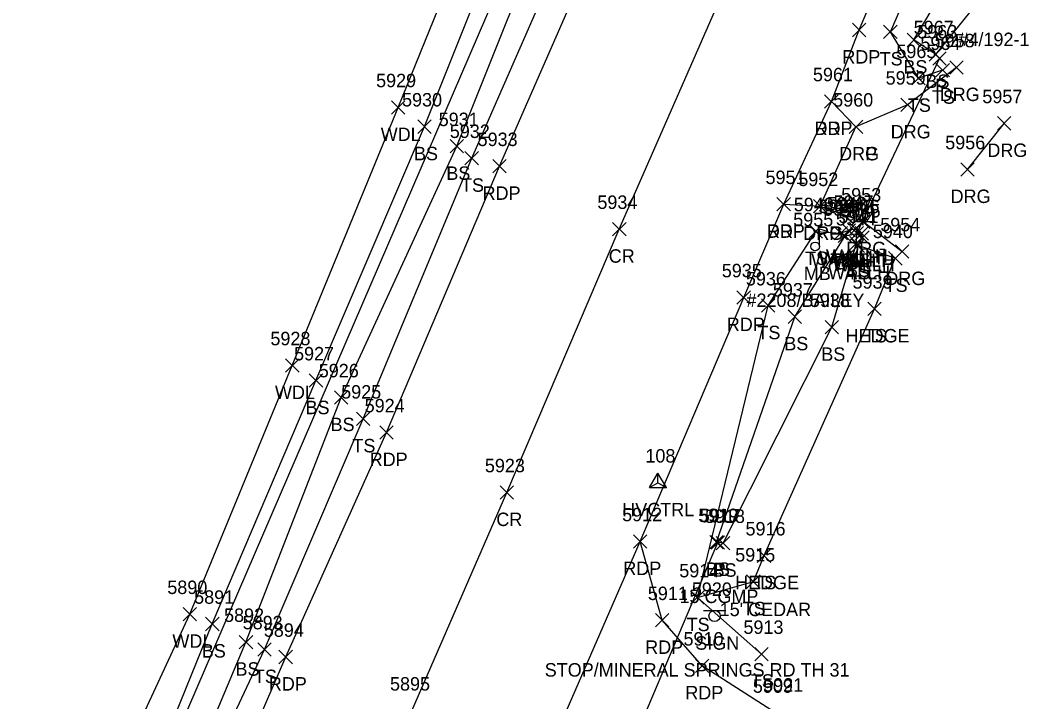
# Model space of a CAD drawing. Extents: x 1611797 to 1633212, y 298978 to 305475.
# Drawn here: x 1622670.8 to 1622821.6, y 301645.8 to 301747.1 of the extents above; entities that cross this region are included whole.
import ezdxf

# ---------------------------------------------------------------- set-up
doc = ezdxf.new("R2010")
doc.units = 0
for name, color, linetype in [('C_A', 7, 'Continuous'), ('C_I', 7, 'Continuous'), ('CPSM', 7, 'Continuous'), ('D_A', 7, 'Continuous'), ('D_C', 7, 'Continuous'), ('D_I', 7, 'Continuous'), ('D_TIC', 7, 'Continuous'), ('DCP', 7, 'Continuous'), ('DHW', 7, 'Continuous'), ('L_A', 7, 'Continuous'), ('L_C', 7, 'Continuous'), ('L_I', 7, 'Continuous'), ('L_TIC', 7, 'Continuous'), ('LAHR', 7, 'Continuous'), ('LAWA', 7, 'Continuous'), ('LELB', 7, 'Continuous'), ('LMB', 7, 'Continuous'), ('P_A', 7, 'Continuous'), ('P_I', 7, 'Continuous'), ('P_TIC', 7, 'Continuous'), ('PET', 7, 'Continuous'), ('PRC', 7, 'Continuous'), ('R_A', 7, 'Continuous'), ('R_I', 7, 'Continuous'), ('R_TIC', 7, 'Continuous'), ('RDG', 7, 'Continuous'), ('RDP', 7, 'Continuous'), ('S_A', 7, 'Continuous'), ('S_C', 7, 'Continuous'), ('S_I', 7, 'Continuous'), ('SSGN', 7, 'Continuous'), ('U_C', 7, 'Continuous')]:
    doc.layers.add(name, color=color, linetype=linetype)

msp = doc.modelspace()

# ---------------------------------------------------------------- linework, layer by layer
at = {"layer": 'CPSM'}
for p, q in [((1622764.35, 301677.62), (1622765.6, 301679.78)), ((1622766.85, 301677.62), (1622765.6, 301679.78)), ((1622765.6, 301678.34), (1622765.6, 301679.78)), ((1622764.35, 301677.62), (1622765.6, 301678.34)), ((1622765.6, 301678.34), (1622765.6, 301678.34)), ((1622765.6, 301678.34), (1622766.85, 301677.62)), ((1622764.35, 301677.62), (1622766.85, 301677.62))]:
    msp.add_line(p, q, dxfattribs=at)
at = {"layer": 'D_TIC'}
for points in [[(1622806.46, 301740.42), (1622808.46, 301742.42)], [(1622808.46, 301740.42), (1622806.46, 301742.42)], [(1622793.98, 301715.07), (1622795.98, 301717.07)], [(1622795.98, 301715.07), (1622793.98, 301717.07)], [(1622791.81, 301714.45), (1622793.81, 301716.45)], [(1622793.81, 301714.45), (1622791.81, 301716.45)], [(1622792.98, 301714.84), (1622794.98, 301716.84)], [(1622794.98, 301714.84), (1622792.98, 301716.84)], [(1622794.17, 301714.43), (1622796.17, 301716.43)], [(1622796.17, 301714.43), (1622794.17, 301716.43)], [(1622794.91, 301714.43), (1622796.91, 301716.43)], [(1622796.91, 301714.43), (1622794.91, 301716.43)], [(1622795.02, 301713.8), (1622797.02, 301715.8)], [(1622797.02, 301713.8), (1622795.02, 301715.8)], [(1622794.32, 301712.6), (1622796.32, 301714.6)], [(1622796.32, 301712.6), (1622794.32, 301714.6)], [(1622773.51, 301668.44), (1622775.51, 301670.44)], [(1622775.51, 301668.44), (1622773.51, 301670.44)]]:
    msp.add_lwpolyline(points, dxfattribs=at)
at = {"layer": 'DCP'}
for points in [[(1622671.2, 301587.84), (1622827.38, 301950.3)], [(1622795.17, 301715.43), (1622807.46, 301741.42)], [(1622757.09, 301628.39), (1622774.51, 301669.44)]]:
    msp.add_lwpolyline(points, dxfattribs=at)
at = {"layer": 'DHW'}
msp.add_lwpolyline([(1622795.32, 301713.6), (1622796.02, 301714.8), (1622795.91, 301715.43), (1622794.98, 301716.07), (1622793.98, 301715.84), (1622792.81, 301715.45)], dxfattribs=at)
at = {"layer": 'L_TIC'}
for points in [[(1622799.16, 301744.4), (1622801.16, 301746.4)], [(1622801.16, 301744.4), (1622799.16, 301746.4)], [(1622802.66, 301743.19), (1622804.66, 301745.19)], [(1622804.66, 301743.19), (1622802.66, 301745.19)], [(1622805.93, 301741.05), (1622807.93, 301743.05)], [(1622807.93, 301741.05), (1622805.93, 301743.05)], [(1622805.93, 301741.05), (1622807.93, 301743.05)], [(1622807.93, 301741.05), (1622805.93, 301743.05)], [(1622806.94, 301738.7), (1622808.94, 301740.7)], [(1622808.94, 301738.7), (1622806.94, 301740.7)], [(1622803.35, 301737.5), (1622805.35, 301739.5)], [(1622805.35, 301737.5), (1622803.35, 301739.5)], [(1622725.95, 301733.16), (1622727.95, 301735.16)], [(1622727.95, 301733.16), (1622725.95, 301735.16)], [(1622729.88, 301730.3), (1622731.88, 301732.3)], [(1622731.88, 301730.3), (1622729.88, 301732.3)], [(1622734.69, 301727.38), (1622736.69, 301729.38)], [(1622736.69, 301727.38), (1622734.69, 301729.38)], [(1622736.9, 301725.61), (1622738.9, 301727.61)], [(1622738.9, 301725.61), (1622736.9, 301727.61)], [(1622788.07, 301714.72), (1622790.07, 301716.72)], [(1622790.07, 301714.72), (1622788.07, 301716.72)], [(1622791.81, 301714.45), (1622793.81, 301716.45)], [(1622793.81, 301714.45), (1622791.81, 301716.45)], [(1622792.42, 301714.05), (1622794.42, 301716.05)], [(1622794.42, 301714.05), (1622792.42, 301716.05)], [(1622794.17, 301714.43), (1622796.17, 301716.43)], [(1622796.17, 301714.43), (1622794.17, 301716.43)], [(1622794.17, 301714.43), (1622796.17, 301716.43)], [(1622796.17, 301714.43), (1622794.17, 301716.43)], [(1622794.13, 301712.96), (1622796.13, 301714.96)], [(1622796.13, 301712.96), (1622794.13, 301714.96)], [(1622794.32, 301712.6), (1622796.32, 301714.6)], [(1622796.32, 301712.6), (1622794.32, 301714.6)], [(1622799.9, 301710.72), (1622801.9, 301712.72)], [(1622801.9, 301710.72), (1622799.9, 301712.72)], [(1622780.99, 301703.68), (1622782.99, 301705.68)], [(1622782.99, 301703.68), (1622780.99, 301705.68)], [(1622796.81, 301703.2), (1622798.81, 301705.2)], [(1622798.81, 301703.2), (1622796.81, 301705.2)], [(1622796.81, 301703.2), (1622798.81, 301705.2)], [(1622798.81, 301703.2), (1622796.81, 301705.2)], [(1622784.95, 301702.03), (1622786.95, 301704.03)], [(1622786.95, 301702.03), (1622784.95, 301704.03)], [(1622790.45, 301700.47), (1622792.45, 301702.47)], [(1622792.45, 301700.47), (1622790.45, 301702.47)], [(1622710.22, 301694.78), (1622712.22, 301696.78)], [(1622712.22, 301694.78), (1622710.22, 301696.78)], [(1622713.74, 301692.53), (1622715.74, 301694.53)], [(1622715.74, 301692.53), (1622713.74, 301694.53)], [(1622717.47, 301690.01), (1622719.47, 301692.01)], [(1622719.47, 301690.01), (1622717.47, 301692.01)], [(1622720.75, 301686.85), (1622722.75, 301688.85)], [(1622722.75, 301686.85), (1622720.75, 301688.85)], [(1622773.3, 301668.48), (1622775.3, 301670.48)], [(1622775.3, 301668.48), (1622773.3, 301670.48)], [(1622774.28, 301668.35), (1622776.28, 301670.35)], [(1622776.28, 301668.35), (1622774.28, 301670.35)], [(1622774.28, 301668.35), (1622776.28, 301670.35)], [(1622776.28, 301668.35), (1622774.28, 301670.35)], [(1622780.37, 301666.49), (1622782.37, 301668.49)], [(1622782.37, 301666.49), (1622780.37, 301668.49)], [(1622780.37, 301666.49), (1622782.37, 301668.49)], [(1622782.37, 301666.49), (1622780.37, 301668.49)], [(1622778.79, 301662.62), (1622780.79, 301664.62)], [(1622780.79, 301662.62), (1622778.79, 301664.62)], [(1622770.46, 301660.26), (1622772.46, 301662.26)], [(1622772.46, 301660.26), (1622770.46, 301662.26)], [(1622770.46, 301660.26), (1622772.46, 301662.26)], [(1622772.46, 301660.26), (1622770.46, 301662.26)], [(1622694.98, 301657.78), (1622696.98, 301659.78)], [(1622696.98, 301657.78), (1622694.98, 301659.78)], [(1622698.32, 301656.33), (1622700.32, 301658.33)], [(1622700.32, 301656.33), (1622698.32, 301658.33)], [(1622703.33, 301653.63), (1622705.33, 301655.63)], [(1622705.33, 301653.63), (1622703.33, 301655.63)], [(1622706.1, 301652.53), (1622708.1, 301654.53)], [(1622708.1, 301652.53), (1622706.1, 301654.53)], [(1622780, 301651.85), (1622782, 301653.85)], [(1622782, 301651.85), (1622780, 301653.85)]]:
    msp.add_lwpolyline(points, dxfattribs=at)
at = {"layer": 'LAHR'}
msp.add_lwpolyline([(1622781.37, 301667.49), (1622797.81, 301704.2)], dxfattribs=at)
at = {"layer": 'LAWA'}
msp.add_lwpolyline([(1622629.31, 301519.57), (1622648.55, 301554.37), (1622664.62, 301587.8), (1622679.92, 301624.12), (1622695.98, 301658.78), (1622711.22, 301695.78), (1622726.95, 301734.16), (1622740.87, 301768.52), (1622755.14, 301811.42), (1622771.04, 301843.63), (1622788.09, 301881.91), (1622808.18, 301922.72), (1622823.47, 301955.6), (1622839.78, 301995.94), (1622853.69, 302036.53), (1622871.34, 302077.8), (1622889.2, 302115.36), (1622900.36, 302148.59), (1622922.7, 302194.91), (1622935.02, 302227), (1622955.61, 302269.3), (1622974.66, 302322.11)], dxfattribs=at)
at = {"layer": 'LELB'}
for points in [[(1622643, 301512.06), (1622661.31, 301549.35), (1622677.51, 301586.51), (1622691.37, 301620.02), (1622707.1, 301653.53), (1622721.75, 301687.85), (1622737.9, 301726.61), (1622754.91, 301765.49), (1622771.04, 301804.05), (1622784.95, 301836.58), (1622802.84, 301876.81), (1622819.3, 301916.18), (1622833.77, 301948.78), (1622851.03, 301989.78), (1622867.88, 302029.76), (1622885.49, 302071.56), (1622902.14, 302111.43), (1622917.02, 302143.8), (1622935.82, 302186.87), (1622950.2, 302222.12), (1622969.04, 302263.04)], [(1622807.94, 301739.7), (1622804.35, 301738.5), (1622800.16, 301745.4), (1622817.14, 301784.47), (1622830.39, 301816.56), (1622848.44, 301857.01), (1622864.13, 301895.69), (1622879.47, 301932.48), (1622894.46, 301967.7), (1622913.22, 302010.21), (1622930.46, 302050.66), (1622949.02, 302093.66), (1622977.04, 302156.2), (1622983.26, 302165.57), (1622999.14, 302167.9)], [(1622594.68, 301439.81), (1622595.31, 301437.14), (1622596.39, 301436.56), (1622598.61, 301436.87), (1622605.11, 301452.44), (1622623.3, 301484.96), (1622638.71, 301514.37), (1622656.97, 301550.94), (1622672.9, 301585.85), (1622690.2, 301620.98), (1622704.33, 301654.63), (1622718.47, 301691.01), (1622735.69, 301728.38), (1622751, 301766.72), (1622767.76, 301805.21), (1622781.52, 301838.57), (1622799.78, 301877.75), (1622815.96, 301917.88), (1622831.89, 301949.85), (1622847.11, 301991.62), (1622864.58, 302030.86), (1622881.19, 302073.91), (1622897.69, 302112.61), (1622900.36, 302148.59)], [(1622594.68, 301439.81), (1622601.87, 301453.13), (1622619.23, 301487.68), (1622635.73, 301516.83), (1622653.65, 301552.16), (1622669.95, 301587.77), (1622685.32, 301622.84), (1622699.32, 301657.33), (1622714.74, 301693.53), (1622730.88, 301731.3), (1622746.12, 301769.47), (1622759.32, 301807.94), (1622775.78, 301841.76), (1622793.88, 301879.63), (1622811.29, 301920.97), (1622825.77, 301951.79), (1622844.08, 301994.2), (1622859.8, 302033.13), (1622878.46, 302076.5), (1622894.74, 302113.74), (1622900.36, 302148.59)], [(1622806.93, 301742.05), (1622803.66, 301744.19), (1622825.75, 301781.18), (1622835.8, 301814.35)], [(1622806.93, 301742.05), (1622835.85, 301777.79)], [(1622781, 301652.85), (1622771.46, 301661.26), (1622781.99, 301704.68), (1622789.07, 301715.72), (1622792.81, 301715.45)], [(1622775.28, 301669.35), (1622774.3, 301669.48), (1622785.95, 301703.03), (1622793.42, 301715.05), (1622795.17, 301715.43)], [(1622775.28, 301669.35), (1622791.45, 301701.47), (1622795.13, 301713.96), (1622795.17, 301715.43)], [(1622797.81, 301704.2), (1622800.9, 301711.72), (1622795.32, 301713.6)], [(1622771.46, 301661.26), (1622779.79, 301663.62), (1622781.37, 301667.49)]]:
    msp.add_lwpolyline(points, dxfattribs=at)
at = {"layer": 'LMB'}
for p, q in [((1622789.63, 301716.08), (1622790.93, 301715.7)), ((1622789.64, 301713.49), (1622789.64, 301716.08)), ((1622789.64, 301715.18), (1622790.92, 301715.69)), ((1622788.98, 301713.48), (1622788.98, 301713.48))]:
    msp.add_line(p, q, dxfattribs=at)
msp.add_circle((1622788.98, 301713.48), 0.656, dxfattribs=at)
at = {"layer": 'P_TIC'}
for points in [[(1622794.53, 301744.68), (1622796.53, 301746.68)], [(1622796.53, 301744.68), (1622794.53, 301746.68)], [(1622790.39, 301734.05), (1622792.39, 301736.05)], [(1622792.39, 301734.05), (1622790.39, 301736.05)], [(1622741.04, 301724.41), (1622743.04, 301726.41)], [(1622743.04, 301724.41), (1622741.04, 301726.41)], [(1622783.3, 301718.76), (1622785.3, 301720.76)], [(1622785.3, 301718.76), (1622783.3, 301720.76)], [(1622758.85, 301715.06), (1622760.85, 301717.06)], [(1622760.85, 301715.06), (1622758.85, 301717.06)], [(1622777.35, 301704.89), (1622779.35, 301706.89)], [(1622779.35, 301704.89), (1622777.35, 301706.89)], [(1622724.24, 301684.81), (1622726.24, 301686.81)], [(1622726.24, 301684.81), (1622724.24, 301686.81)], [(1622742.12, 301675.89), (1622744.12, 301677.89)], [(1622744.12, 301675.89), (1622742.12, 301677.89)], [(1622761.96, 301668.6), (1622763.96, 301670.6)], [(1622763.96, 301668.6), (1622761.96, 301670.6)], [(1622761.96, 301668.6), (1622763.96, 301670.6)], [(1622763.96, 301668.6), (1622761.96, 301670.6)], [(1622765.22, 301656.88), (1622767.22, 301658.88)], [(1622767.22, 301656.88), (1622765.22, 301658.88)], [(1622709.24, 301651.42), (1622711.24, 301653.42)], [(1622711.24, 301651.42), (1622709.24, 301653.42)], [(1622771.18, 301650.11), (1622773.18, 301652.11)], [(1622773.18, 301650.11), (1622771.18, 301652.11)]]:
    msp.add_lwpolyline(points, dxfattribs=at)
at = {"layer": 'PET'}
for points in [[(1622648.26, 301509.67), (1622665.21, 301547.65), (1622681.33, 301585.73), (1622695.37, 301617.98), (1622710.24, 301652.42), (1622725.24, 301685.81), (1622742.04, 301725.41), (1622758.88, 301763.93), (1622775.24, 301802.31), (1622789.18, 301834.69), (1622806.59, 301875.58), (1622823.24, 301913.81), (1622837.58, 301947.53), (1622854.56, 301988.08), (1622872.12, 302028.45), (1622889.38, 302069.51), (1622906.69, 302110.12), (1622920.84, 302142.69), (1622939.57, 302184.64), (1622954.91, 302220.6), (1622972.44, 302261.85)], [(1622698.78, 301521.43), (1622708.15, 301542.48), (1622718.91, 301567.6), (1622732.31, 301598.1), (1622748.3, 301635.86), (1622762.96, 301669.6), (1622778.35, 301705.89), (1622784.3, 301719.76), (1622791.39, 301735.05), (1622795.53, 301745.68), (1622812.78, 301786.17), (1622826.49, 301818.45), (1622843.67, 301858.56), (1622860.37, 301897.43), (1622876.1, 301933.63), (1622891.74, 301969.78), (1622909.96, 302011.85), (1622927.46, 302052.61), (1622945.32, 302094.8), (1622972.71, 302158.13)], [(1622748.3, 301635.86), (1622755.21, 301637.93), (1622765.81, 301636.97), (1622774.83, 301631.24), (1622783.06, 301644.09), (1622772.18, 301651.11), (1622766.22, 301657.88), (1622762.96, 301669.6)]]:
    msp.add_lwpolyline(points, dxfattribs=at)
at = {"layer": 'PRC'}
msp.add_lwpolyline([(1622666.77, 301501.34), (1622684.44, 301540.78), (1622698.59, 301575.31), (1622713.87, 301609.52), (1622729.01, 301644.42), (1622743.12, 301676.89), (1622759.85, 301716.06), (1622777.36, 301756.12), (1622793.76, 301794.22), (1622808.13, 301826.76), (1622825.32, 301867.31), (1622841.48, 301905.46), (1622856.61, 301940.95), (1622872.28, 301978.08), (1622890.25, 302020.71), (1622907.64, 302061.05), (1622925.87, 302103.21), (1622941.24, 302138.62), (1622957.15, 302175.75), (1622973.3, 302212.68)], dxfattribs=at)
at = {"layer": 'R_TIC'}
for points in [[(1622809.01, 301739.1), (1622811.01, 301741.1)], [(1622811.01, 301739.1), (1622809.01, 301741.1)], [(1622790.39, 301734.05), (1622792.39, 301736.05)], [(1622792.39, 301734.05), (1622790.39, 301736.05)], [(1622801.73, 301733.55), (1622803.73, 301735.55)], [(1622803.73, 301733.55), (1622801.73, 301735.55)], [(1622794.05, 301730.28), (1622796.05, 301732.28)], [(1622796.05, 301730.28), (1622794.05, 301732.28)], [(1622794.05, 301730.28), (1622796.05, 301732.28)], [(1622796.05, 301730.28), (1622794.05, 301732.28)], [(1622816.1, 301730.79), (1622818.1, 301732.79)], [(1622818.1, 301730.79), (1622816.1, 301732.79)], [(1622810.63, 301723.94), (1622812.63, 301725.94)], [(1622812.63, 301723.94), (1622810.63, 301725.94)], [(1622783.3, 301718.76), (1622785.3, 301720.76)], [(1622785.3, 301718.76), (1622783.3, 301720.76)], [(1622788.73, 301718.46), (1622790.73, 301720.46)], [(1622790.73, 301718.46), (1622788.73, 301720.46)], [(1622788.73, 301718.46), (1622790.73, 301720.46)], [(1622790.73, 301718.46), (1622788.73, 301720.46)], [(1622795.11, 301716.17), (1622797.11, 301718.17)], [(1622797.11, 301716.17), (1622795.11, 301718.17)], [(1622800.92, 301711.73), (1622802.92, 301713.73)], [(1622802.92, 301711.73), (1622800.92, 301713.73)]]:
    msp.add_lwpolyline(points, dxfattribs=at)
at = {"layer": 'RDG'}
for points in [[(1622810.01, 301740.1), (1622802.73, 301734.55), (1622795.05, 301731.28)], [(1622811.63, 301724.94), (1622817.1, 301731.79)], [(1622789.73, 301719.46), (1622796.11, 301717.17), (1622801.92, 301712.73)]]:
    msp.add_lwpolyline(points, dxfattribs=at)
at = {"layer": 'RDP'}
msp.add_lwpolyline([(1622784.3, 301719.76), (1622789.73, 301719.46), (1622795.05, 301731.28), (1622791.39, 301735.05)], dxfattribs=at)
at = {"layer": 'SSGN'}
for p, q in [((1622772.36, 301659.35), (1622775.7, 301659.35)), ((1622774.01, 301658.52), (1622774.01, 301658.52))]:
    msp.add_line(p, q, dxfattribs=at)
msp.add_circle((1622774.01, 301658.52), 0.833, dxfattribs=at)

# ---------------------------------------------------------------- texts
at = {"layer": 'C_A'}
msp.add_text('HVCTRL', height=2, dxfattribs=at).set_placement((1622760.29, 301673.34))
at = {"layer": 'C_I'}
msp.add_text('108', height=2, dxfattribs=at).set_placement((1622763.73, 301681.34))
at = {"layer": 'D_A'}
for s, p in [('P', (1622806.84, 301736.42)), ('WALLH', (1622789.57, 301710.84)), ('WALLH', (1622790.57, 301711.07)), ('WALLH', (1622788.4, 301710.45)), ('WALLH', (1622791.5, 301710.43)), ('WALLH', (1622791.61, 301709.8)), ('P', (1622794.55, 301710.43)), ('WALLH', (1622790.92, 301708.6)), ('P', (1622773.88, 301664.44))]:
    msp.add_text(s, height=2, dxfattribs=at).set_placement(p)
at = {"layer": 'D_C'}
msp.add_text('15 CGMP', height=2, dxfattribs=at).set_placement((1622768.8, 301660.44))
at = {"layer": 'D_I'}
for s, p in [('5963', (1622804.16, 301744.42)), ('5950', (1622789.46, 301718.45)), ('5948', (1622790.72, 301718.84)), ('5947', (1622791.72, 301719.07)), ('5943', (1622791.91, 301718.43)), ('5946', (1622792.6, 301718.43)), ('5944', (1622792.06, 301716.6)), ('5945', (1622792.76, 301717.8)), ('5917', (1622771.81, 301672.44))]:
    msp.add_text(s, height=2, dxfattribs=at).set_placement(p)
at = {"layer": 'L_A'}
for s, p in [('TS', (1622798.57, 301740.4)), ('BS', (1622802.1, 301739.19)), ('BS', (1622805.38, 301737.05)), ('BS', (1622805.38, 301737.05)), ('TS', (1622806.35, 301734.7)), ('TS', (1622802.76, 301733.5)), ('WDL', (1622724.37, 301729.16)), ('BS', (1622729.32, 301726.3)), ('BS', (1622734.13, 301723.38)), ('TS', (1622736.31, 301721.61)), ('TS', (1622787.48, 301710.72)), ('TS', (1622791.22, 301710.45)), ('BS', (1622791.86, 301710.05)), ('BS', (1622793.61, 301710.43)), ('BS', (1622793.61, 301710.43)), ('MB', (1622787.29, 301708.48)), ('BS', (1622793.57, 301708.96)), ('TS', (1622793.73, 301708.6)), ('TS', (1622799.31, 301706.72)), ('TS', (1622780.39, 301699.68)), ('HEDGE', (1622793.51, 301699.2)), ('TS', (1622796.22, 301699.2)), ('BS', (1622784.39, 301698.03)), ('BS', (1622789.89, 301696.47)), ('WDL', (1622708.64, 301690.78)), ('BS', (1622713.19, 301688.53)), ('BS', (1622716.91, 301686.01)), ('TS', (1622720.16, 301682.85)), ('BS', (1622772.74, 301664.48)), ('BS', (1622773.72, 301664.35)), ('BS', (1622773.72, 301664.35)), ('HEDGE', (1622777.07, 301662.49)), ('TS', (1622779.78, 301662.49)), ('TS', (1622778.2, 301658.62)), ('TS', (1622769.87, 301656.26)), ('TS', (1622769.87, 301656.26)), ('WDL', (1622693.39, 301653.78)), ('BS', (1622697.76, 301652.33)), ('BS', (1622702.77, 301649.63)), ('TS', (1622705.51, 301648.53)), ('TS', (1622779.41, 301647.85))]:
    msp.add_text(s, height=2, dxfattribs=at).set_placement(p)
at = {"layer": 'L_C'}
for s, p in [('#2208/BAILEY', (1622778.76, 301704.48)), ("15' CEDAR", (1622774.78, 301658.49))]:
    msp.add_text(s, height=2, dxfattribs=at).set_placement(p)
at = {"layer": 'L_I'}
for s, p in [('5967', (1622803.63, 301745.05)), ('5967', (1622803.63, 301745.05)), ('5964', (1622804.63, 301742.7)), ('5965', (1622801.05, 301741.5)), ('5929', (1622723.68, 301737.16)), ('5930', (1622727.54, 301734.3)), ('5931', (1622732.99, 301731.38)), ('5932', (1622734.64, 301729.61)), ('5949', (1622785.8, 301718.72)), ('5950', (1622789.46, 301718.45)), ('5943', (1622791.91, 301718.43)), ('5943', (1622791.91, 301718.43)), ('5942', (1622790.16, 301718.05)), ('5944', (1622792.06, 301716.6)), ('5941', (1622792.44, 301716.96)), ('5955', (1622785.72, 301716.48)), ('5940', (1622797.55, 301714.72)), ('5936', (1622778.67, 301707.68)), ('5937', (1622782.69, 301706.03)), ('5939', (1622794.54, 301707.2)), ('5939', (1622794.54, 301707.2)), ('5938', (1622788.19, 301704.47)), ('5928', (1622707.96, 301698.78)), ('5927', (1622711.48, 301696.53)), ('5926', (1622715.15, 301694.01)), ('5925', (1622718.49, 301690.85)), ('5919', (1622771.6, 301672.48)), ('5918', (1622772.59, 301672.35)), ('5918', (1622772.59, 301672.35)), ('5916', (1622778.62, 301670.49)), ('5916', (1622778.62, 301670.49)), ('5915', (1622777.09, 301666.62)), ('5914', (1622768.77, 301664.26)), ('5914', (1622768.77, 301664.26)), ('5890', (1622692.63, 301661.78)), ('5891', (1622696.62, 301660.33)), ('5892', (1622701.07, 301657.63)), ('5893', (1622703.84, 301656.53)), ('5913', (1622778.31, 301655.85))]:
    msp.add_text(s, height=2, dxfattribs=at).set_placement(p)
at = {"layer": 'P_A'}
for s, p in [('RDP', (1622793.02, 301740.68)), ('RDP', (1622788.88, 301730.05)), ('RDP', (1622739.52, 301720.41)), ('RDP', (1622781.79, 301714.76)), ('CR', (1622758.28, 301711.06)), ('RDP', (1622775.84, 301700.89)), ('RDP', (1622722.73, 301680.81)), ('CR', (1622741.56, 301671.89)), ('RDP', (1622760.45, 301664.6)), ('RDP', (1622760.45, 301664.6)), ('RDP', (1622763.7, 301652.88)), ('RDP', (1622707.73, 301647.42)), ('RDP', (1622769.67, 301646.11))]:
    msp.add_text(s, height=2, dxfattribs=at).set_placement(p)
at = {"layer": 'P_I'}
for s, p in [('5961', (1622788.65, 301738.05)), ('5933', (1622738.78, 301728.41)), ('5951', (1622781.6, 301722.76)), ('5934', (1622756.59, 301719.06)), ('5935', (1622775.09, 301708.89)), ('5924', (1622721.98, 301688.81)), ('5923', (1622739.86, 301679.89)), ('5912', (1622760.27, 301672.6)), ('5912', (1622760.27, 301672.6)), ('5911', (1622764.09, 301660.88)), ('5894', (1622706.98, 301655.42)), ('5910', (1622769.4, 301654.11)), ('5895', (1622725.75, 301647.42)), ('5921', (1622781.25, 301647.26)), ('5909', (1622779.71, 301647.09)), ('5909', (1622779.71, 301647.09))]:
    msp.add_text(s, height=2, dxfattribs=at).set_placement(p)
at = {"layer": 'R_A'}
for s, p in [('DRG', (1622807.5, 301735.1)), ('DRP', (1622788.88, 301730.05)), ('DRG', (1622800.21, 301729.55)), ('DRG', (1622792.54, 301726.28)), ('DRP', (1622792.54, 301726.28)), ('DRG', (1622814.59, 301726.79)), ('DRG', (1622809.12, 301719.94)), ('DRP', (1622781.79, 301714.76)), ('DRG', (1622787.21, 301714.46)), ('DRP', (1622787.21, 301714.46)), ('DRG', (1622793.6, 301712.17)), ('DRG', (1622799.41, 301707.73))]:
    msp.add_text(s, height=2, dxfattribs=at).set_placement(p)
at = {"layer": 'R_I'}
for s, p in [('5958', (1622806.75, 301743.1)), ('5961', (1622788.65, 301738.05)), ('5959', (1622799.46, 301737.55)), ('5957', (1622813.84, 301734.79)), ('5960', (1622791.66, 301734.28)), ('5960', (1622791.66, 301734.28)), ('5956', (1622808.32, 301727.94)), ('5951', (1622781.6, 301722.76)), ('5952', (1622786.47, 301722.46)), ('5952', (1622786.47, 301722.46)), ('5953', (1622792.85, 301720.17)), ('5954', (1622798.66, 301715.73))]:
    msp.add_text(s, height=2, dxfattribs=at).set_placement(p)
at = {"layer": 'S_A'}
msp.add_text('SIGN', height=2, dxfattribs=at).set_placement((1622771.15, 301653.5))
at = {"layer": 'S_C'}
msp.add_text('STOP/MINERAL SPRINGS RD TH 31', height=2, dxfattribs=at).set_placement((1622748.76, 301649.5))
at = {"layer": 'S_I'}
msp.add_text('5920', height=2, dxfattribs=at).set_placement((1622770.64, 301661.5))
at = {"layer": 'U_C'}
msp.add_text('#4/192-1', height=2, dxfattribs=at).set_placement((1622810.29, 301743.28))

doc.saveas('drawing.dxf')
